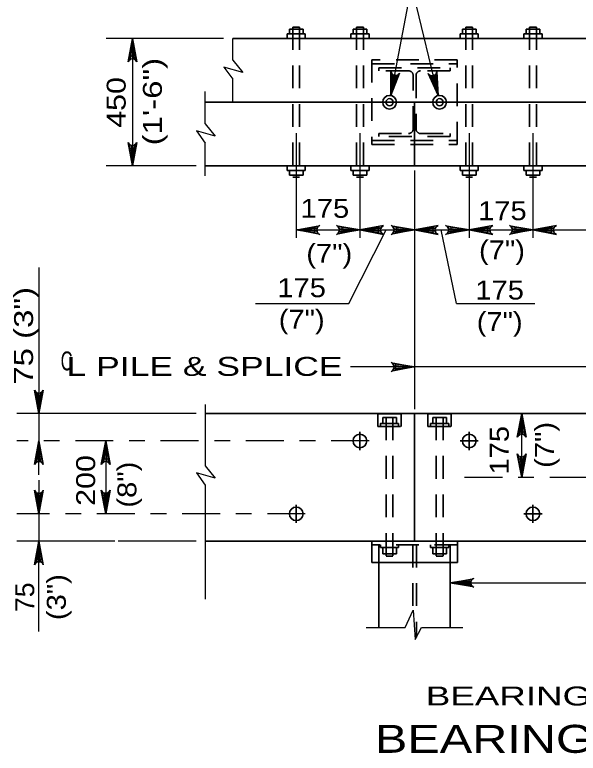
# Model space of a CAD drawing. Extents: x -6.4 to 73.1, y -66 to 0.
# Drawn here: x 57.112 to 60.681, y -50.985 to -46.309 of the extents above; entities that cross this region are included whole.
import ezdxf
from ezdxf.enums import TextEntityAlignment as Align

# ---------------------------------------------------------------- set-up
doc = ezdxf.new("R2010")
doc.units = 0
doc.header["$LTSCALE"] = 0.048
doc.linetypes.add('DOT_DASHED', pattern=[7.7, 5, -1.2, 0.3, -1.2])
doc.linetypes.add('MEDIUM_DASHED', pattern=[4.5, 3, -1.5])
for name, color, linetype, lineweight in [('3', 7, 'Continuous', 35), ('4', 7, 'Continuous', 25), ('5', 7, 'Continuous', 25)]:
    doc.layers.add(name, color=color, linetype=linetype, lineweight=lineweight)

msp = doc.modelspace()

# ---------------------------------------------------------------- hatches: boundary and pattern name
at = {"layer": '4'}
for points in [[(57.83867, -46.56917), (57.87558, -46.56917), (57.85717, -46.4585)], [(57.83867, -47.15508), (57.87558, -47.15508), (57.85717, -47.26583)], [(59.00967, -47.652), (59.00967, -47.69042), (58.89433, -47.67117)], [(59.18267, -47.652), (59.18267, -47.69042), (59.298, -47.67117)], [(59.41333, -47.652), (59.41333, -47.69042), (59.298, -47.67117)], [(59.52867, -47.652), (59.52867, -47.69042), (59.64408, -47.67117)], [(59.75942, -47.652), (59.75942, -47.69042), (59.64408, -47.67117)], [(59.87475, -47.652), (59.87475, -47.69042), (59.99008, -47.67117)], [(60.10542, -47.652), (60.10542, -47.69042), (59.99008, -47.67117)], [(60.27842, -47.652), (60.27842, -47.69042), (60.39375, -47.67117)], [(60.50908, -47.652), (60.50908, -47.69042), (60.39375, -47.67117)], [(59.52392, -48.51992), (59.52392, -48.55842), (59.63925, -48.53917)], [(57.28358, -48.71942), (57.24517, -48.71942), (57.26433, -48.83475)], [(60.30333, -48.95008), (60.34175, -48.95008), (60.3225, -48.83475)], [(57.28358, -49.12308), (57.24517, -49.12308), (57.26433, -49.00775)], [(57.70708, -49.12308), (57.66858, -49.12308), (57.68783, -49.00775)], [(60.34175, -49.12308), (60.30333, -49.12308), (60.3225, -49.2385)], [(57.28358, -49.35383), (57.24517, -49.35383), (57.26433, -49.46917)], [(57.70708, -49.35383), (57.66858, -49.35383), (57.68783, -49.46917)], [(57.28358, -49.7575), (57.24517, -49.7575), (57.26433, -49.64217)]]:
    msp.add_hatch(color=256, dxfattribs=at).paths.add_polyline_path(points)

# ---------------------------------------------------------------- linework, layer by layer
at = {"layer": '3'}
for p, q in [((58.87267, -46.38633), (58.91592, -46.38633)), ((59.27642, -46.38633), (59.31967, -46.38633)), ((59.96842, -46.38633), (60.01167, -46.38633)), ((60.37217, -46.38633), (60.41542, -46.38633)), ((58.83667, -46.42958), (58.952, -46.42958)), ((58.83667, -46.4585), (58.83667, -46.42958)), ((58.85108, -46.40075), (58.93758, -46.40075)), ((58.85108, -46.42958), (58.85108, -46.40075)), ((58.93758, -46.42958), (58.93758, -46.40075)), ((58.952, -46.4585), (58.952, -46.42958)), ((59.25475, -46.42958), (59.25475, -46.40075)), ((59.25475, -46.40075), (59.34125, -46.40075)), ((59.34125, -46.42958), (59.34125, -46.40075)), ((59.35567, -46.4585), (59.35567, -46.42958)), ((59.93242, -46.42958), (60.04775, -46.42958)), ((59.93242, -46.4585), (59.93242, -46.42958)), ((59.94683, -46.42958), (59.94683, -46.40075)), ((59.94683, -46.40075), (60.03333, -46.40075)), ((60.03333, -46.42958), (60.03333, -46.40075)), ((60.04775, -46.4585), (60.04775, -46.42958)), ((60.33608, -46.4585), (60.33608, -46.42958)), ((60.33608, -46.42958), (60.45142, -46.42958)), ((60.3505, -46.42958), (60.3505, -46.40075)), ((60.3505, -46.40075), (60.437, -46.40075)), ((60.437, -46.42958), (60.437, -46.40075)), ((60.45142, -46.4585), (60.45142, -46.42958)), ((64.62167, -46.4585), (58.49208, -46.4585)), ((64.79608, -46.86217), (58.31758, -46.86217)), ((59.64408, -46.86217), (59.64408, -47.26583)), ((64.79608, -47.26583), (58.31758, -47.26583)), ((58.83667, -47.26583), (58.83667, -47.29467)), ((58.952, -47.26583), (58.952, -47.29467)), ((59.24033, -47.26583), (59.24033, -47.29467)), ((59.35567, -47.26583), (59.35567, -47.29467)), ((59.93242, -47.26583), (59.93242, -47.29467)), ((60.04775, -47.26583), (60.04775, -47.29467)), ((60.33608, -47.26583), (60.33608, -47.29467)), ((60.45142, -47.26583), (60.45142, -47.29467)), ((58.83667, -47.29467), (58.952, -47.29467)), ((58.85108, -47.29467), (58.85108, -47.3235)), ((58.85108, -47.3235), (58.93758, -47.3235)), ((58.93758, -47.29467), (58.93758, -47.3235)), ((59.24033, -47.29467), (59.35567, -47.29467)), ((59.25475, -47.29467), (59.25475, -47.3235)), ((59.25475, -47.3235), (59.34125, -47.3235)), ((59.34125, -47.29467), (59.34125, -47.3235)), ((59.93242, -47.29467), (60.04775, -47.29467)), ((59.94683, -47.29467), (59.94683, -47.3235)), ((59.94683, -47.3235), (60.03333, -47.3235)), ((60.03333, -47.29467), (60.03333, -47.3235)), ((60.33608, -47.29467), (60.45142, -47.29467)), ((60.3505, -47.29467), (60.3505, -47.3235)), ((60.3505, -47.3235), (60.437, -47.3235)), ((60.437, -47.29467), (60.437, -47.3235)), ((58.87267, -47.33792), (58.91592, -47.33792)), ((59.27642, -47.33792), (59.31967, -47.33792)), ((59.96842, -47.33792), (60.01167, -47.33792)), ((60.37217, -47.33792), (60.41542, -47.33792)), ((64.79608, -48.83475), (58.31758, -48.83475)), ((59.44225, -48.89808), (59.44225, -48.8585)), ((59.44225, -48.8585), (59.52875, -48.8585)), ((59.52875, -48.89808), (59.52875, -48.8585)), ((59.64408, -48.83475), (59.64408, -49.64217)), ((59.75942, -48.89808), (59.75942, -48.8585)), ((59.75942, -48.8585), (59.84592, -48.8585)), ((59.84592, -48.89808), (59.84592, -48.8585)), ((59.54317, -48.91625), (59.54317, -48.89808)), ((59.86033, -48.91625), (59.86033, -48.89808)), ((59.298, -48.95008), (59.298, -49.06542)), ((59.99008, -48.95008), (59.99008, -49.06542)), ((60.04775, -49.00775), (59.93242, -49.00775)), ((58.89433, -49.4115), (58.89433, -49.52683)), ((60.39375, -49.4115), (60.39375, -49.52683)), ((60.45142, -49.46917), (60.33608, -49.46917)), ((64.79608, -49.64217), (58.31758, -49.64217)), ((59.37325, -49.64217), (59.37325, -49.77717)), ((59.42783, -49.66467), (59.42783, -49.68275)), ((59.54317, -49.66467), (59.54317, -49.68275)), ((59.745, -49.66467), (59.745, -49.68275)), ((59.86033, -49.66467), (59.86033, -49.68275)), ((59.91492, -49.64217), (59.91492, -49.77717)), ((59.42783, -49.68275), (59.54317, -49.68275)), ((59.44225, -49.68275), (59.44225, -49.72233)), ((59.52875, -49.68275), (59.52875, -49.72233)), ((59.745, -49.68275), (59.86033, -49.68275)), ((59.75942, -49.68275), (59.75942, -49.72233)), ((59.84592, -49.68275), (59.84592, -49.72233)), ((59.44225, -49.72233), (59.52875, -49.72233)), ((59.46392, -49.73675), (59.50717, -49.73675)), ((59.75942, -49.72233), (59.84592, -49.72233)), ((59.78108, -49.73675), (59.82433, -49.73675)), ((59.91492, -49.77717), (59.37325, -49.77717)), ((59.41825, -49.77717), (59.41825, -50.18858)), ((59.86992, -49.77717), (59.86992, -50.18858))]:
    msp.add_line(p, q, dxfattribs=at)
at = {"layer": '3', "linetype": 'MEDIUM_DASHED'}
for p, q in [((58.87267, -46.38633), (58.87267, -47.33792)), ((58.91592, -46.38633), (58.91592, -47.33792)), ((59.27642, -46.38633), (59.27642, -47.33792)), ((59.31967, -46.38633), (59.31967, -47.33792)), ((59.96842, -46.38633), (59.96842, -47.33792)), ((60.01167, -46.38633), (60.01167, -47.33792)), ((60.37217, -46.38633), (60.37217, -47.33792)), ((60.41542, -46.38633), (60.41542, -47.33792)), ((59.37342, -46.61933), (59.91475, -46.61933)), ((59.63475, -47.032), (59.63475, -46.69233)), ((59.65342, -46.69233), (59.65342, -47.032)), ((59.37342, -47.105), (59.91475, -47.105)), ((59.46392, -48.8585), (59.46392, -49.73675)), ((59.50717, -48.8585), (59.50717, -49.73675)), ((59.78108, -48.8585), (59.78108, -49.73675)), ((59.82433, -48.8585), (59.82433, -49.73675)), ((59.91492, -49.66467), (59.37325, -49.66467)), ((59.41825, -49.66467), (59.41825, -49.77717)), ((59.63283, -49.66467), (59.63283, -50.08625)), ((59.65533, -49.66467), (59.65533, -50.25058)), ((59.86992, -49.66467), (59.86992, -49.77717))]:
    msp.add_line(p, q, dxfattribs=at)
at = {"layer": '3', "lineweight": 25}
for p, q in [((58.49208, -46.59625), (58.49208, -46.4585)), ((58.49208, -46.59625), (58.55542, -46.67417)), ((58.43617, -46.64042), (58.49208, -46.717)), ((58.55542, -46.67417), (58.43617, -46.64042)), ((58.49208, -46.86217), (58.49208, -46.717)), ((58.31758, -46.99992), (58.31758, -46.79483)), ((58.31758, -46.99992), (58.381, -47.07792)), ((58.31758, -47.32908), (58.31758, -47.12067)), ((58.31758, -48.77708), (58.31758, -49.166)), ((58.31758, -49.166), (58.381, -49.244)), ((58.26175, -49.21017), (58.31758, -49.28675)), ((58.381, -49.244), (58.26175, -49.21017)), ((58.31758, -49.28675), (58.31758, -50.00908)), ((59.33783, -50.18858), (59.58458, -50.18858))]:
    msp.add_line(p, q, dxfattribs=at)
at = {"layer": '3'}
for points in [[(59.24033, -46.4585), (59.24033, -46.42958), (59.35567, -46.42958)], [(59.42783, -48.91625), (59.42783, -48.89808), (59.54317, -48.89808)], [(59.745, -48.91625), (59.745, -48.89808), (59.86033, -48.89808)]]:
    msp.add_lwpolyline(points, dxfattribs=at)
at = {"layer": '3', "linetype": 'MEDIUM_DASHED'}
for points in [[(59.37342, -47.13117), (59.91475, -47.13117), (59.91475, -46.59317), (59.37342, -46.59317)], [(59.41167, -48.91625), (59.55933, -48.91625), (59.55933, -48.83483), (59.41167, -48.83483)], [(59.72883, -48.91625), (59.8765, -48.91625), (59.8765, -48.83483), (59.72883, -48.83483)]]:
    msp.add_lwpolyline(points, close=True, dxfattribs=at)
for points in [[(59.41825, -46.64475), (59.86992, -46.64475), (59.86992, -46.66358), (59.68217, -46.66358)], [(59.606, -46.66358), (59.41825, -46.66358), (59.41825, -46.64475)], [(59.68217, -47.06075), (59.86992, -47.06075), (59.86992, -47.07958), (59.41825, -47.07958), (59.41825, -47.06075), (59.606, -47.06075)]]:
    msp.add_lwpolyline(points, dxfattribs=at)
at = {"layer": '3', "lineweight": 25}
for points in [[(58.381, -47.07792), (58.26175, -47.04408), (58.31758, -47.12067)], [(59.58458, -50.18858), (59.63617, -50.07917), (59.6475, -50.26542), (59.68817, -50.18858), (59.94942, -50.18858)]]:
    msp.add_lwpolyline(points, dxfattribs=at)
at = {"layer": '3'}
for centre, radius in [((59.4855, -46.86217), 0.04325), ((59.4855, -46.86217), 0.02242), ((59.80267, -46.86217), 0.04325), ((59.80267, -46.86217), 0.02242), ((59.29804, -49.00774), 0.04325), ((59.99009, -49.00774), 0.04325), ((58.89435, -49.46911), 0.04325), ((60.39379, -49.46911), 0.04325)]:
    msp.add_circle(centre, radius, dxfattribs=at)
at = {"layer": '3', "linetype": 'MEDIUM_DASHED'}
for centre, start, end in [((59.60597, -46.69236), 0, 90), ((59.68219, -46.69236), 90, 180), ((59.60597, -47.03197), 270, 0), ((59.68219, -47.03197), 180, 270)]:
    msp.add_arc(centre, 0.02881, start, end, dxfattribs=at)
at = {"layer": '4'}
for p, q in [((59.49358, -46.81967), (59.62642, -46.12508)), ((59.79258, -46.82008), (59.62642, -46.12508)), ((58.43442, -46.4585), (57.69108, -46.4585)), ((57.85717, -46.4585), (57.85717, -47.26583)), ((58.89433, -47.05917), (58.89433, -47.72075)), ((59.298, -47.05917), (59.298, -47.72075)), ((59.99008, -47.05917), (59.99008, -47.72075)), ((60.39375, -47.05917), (60.39375, -47.72075)), ((58.25992, -47.26583), (57.69108, -47.26583)), ((59.64408, -47.29467), (59.64408, -48.80592)), ((58.89433, -47.67117), (61.55683, -47.67117)), ((59.90917, -48.13783), (59.81175, -47.67108)), ((57.26433, -47.90908), (57.26433, -48.83475)), ((59.90917, -48.13783), (60.40617, -48.13783)), ((63.46975, -48.53908), (59.23808, -48.53908)), ((58.25992, -48.83475), (57.12367, -48.83475)), ((57.26433, -48.83475), (57.26433, -49.00775)), ((60.3225, -49.2385), (60.3225, -48.83475)), ((57.26433, -49.22225), (57.26433, -49.00775)), ((57.68783, -49.00775), (57.68783, -49.46917)), ((57.26433, -49.25542), (57.26433, -49.46917)), ((57.26433, -49.46917), (57.26433, -49.64217)), ((57.74542, -49.64217), (57.12367, -49.64217)), ((57.26433, -50.21358), (57.26433, -49.64217)), ((58.25992, -49.64217), (57.76583, -49.64217)), ((59.86992, -49.90558), (60.852, -49.9055))]:
    msp.add_line(p, q, dxfattribs=at)
at = {"layer": '4', "linetype": 'DOT_DASHED'}
for p, q in [((59.35567, -49.00775), (57.12367, -49.00775)), ((62.90008, -49.2385), (59.867, -49.2385)), ((58.952, -49.46917), (57.12367, -49.46917))]:
    msp.add_line(p, q, dxfattribs=at)
at = {"layer": '4'}
for points in [[(57.85717, -46.4585), (57.88517, -46.60767), (57.87717, -46.59617), (57.86717, -46.59025), (57.85717, -46.5885), (57.84717, -46.59025), (57.83717, -46.59617), (57.82917, -46.60767), (57.85717, -46.4585), (57.83717, -46.59617), (57.84717, -46.59025), (57.85717, -46.4585), (57.85717, -46.5885), (57.86717, -46.59025), (57.85717, -46.4585), (57.87717, -46.59617)], [(59.49358, -46.81967), (59.49417, -46.66792), (59.497, -46.67433), (59.49983, -46.68067), (59.50417, -46.68458), (59.5085, -46.68842), (59.51325, -46.69017), (59.518, -46.692), (59.52308, -46.69208), (59.52817, -46.69217), (59.53358, -46.69017), (59.53908, -46.68825), (59.54408, -46.68333), (59.54908, -46.67842), (59.49358, -46.81967), (59.54408, -46.68333), (59.53908, -46.68825), (59.49358, -46.81967), (59.53358, -46.69017), (59.52817, -46.69217), (59.49358, -46.81967), (59.52308, -46.69208), (59.518, -46.692), (59.49358, -46.81967), (59.51325, -46.69017), (59.5085, -46.68842), (59.49358, -46.81967), (59.50417, -46.68458), (59.49983, -46.68067), (59.49358, -46.81967), (59.497, -46.67433)], [(59.79258, -46.82008), (59.73067, -46.6815), (59.73592, -46.68617), (59.74108, -46.69083), (59.74667, -46.69258), (59.75225, -46.69425), (59.75725, -46.69392), (59.76233, -46.69367), (59.767, -46.69167), (59.77167, -46.68967), (59.77583, -46.68558), (59.78, -46.68158), (59.78258, -46.675), (59.78508, -46.6685), (59.79258, -46.82008), (59.78258, -46.675), (59.78, -46.68158), (59.79258, -46.82008), (59.77583, -46.68558), (59.77167, -46.68967), (59.79258, -46.82008), (59.767, -46.69167), (59.76233, -46.69367), (59.79258, -46.82008), (59.75725, -46.69392), (59.75225, -46.69425), (59.79258, -46.82008), (59.74667, -46.69258), (59.74108, -46.69083), (59.79258, -46.82008), (59.73592, -46.68617)], [(57.85717, -47.26583), (57.82917, -47.11667), (57.83717, -47.12817), (57.84717, -47.13408), (57.85717, -47.13583), (57.86717, -47.13408), (57.87717, -47.12817), (57.88517, -47.11667), (57.85717, -47.26583), (57.87717, -47.12817), (57.86717, -47.13408), (57.85717, -47.26583), (57.85717, -47.13583), (57.84717, -47.13408), (57.85717, -47.26583), (57.83717, -47.12817)], [(58.89433, -47.67117), (59.0435, -47.64317), (59.032, -47.65117), (59.02608, -47.66117), (59.02433, -47.67117), (59.02608, -47.68117), (59.032, -47.69117), (59.0435, -47.69917), (58.89433, -47.67117), (59.032, -47.69117), (59.02608, -47.68117), (58.89433, -47.67117), (59.02433, -47.67117), (59.02608, -47.66117), (58.89433, -47.67117), (59.032, -47.65117)], [(59.298, -47.67117), (59.14883, -47.69917), (59.16033, -47.69117), (59.16625, -47.68117), (59.168, -47.67117), (59.16625, -47.66117), (59.16033, -47.65117), (59.14883, -47.64317), (59.298, -47.67117), (59.16033, -47.65117), (59.16625, -47.66117), (59.298, -47.67117), (59.168, -47.67117), (59.16625, -47.68117), (59.298, -47.67117), (59.16033, -47.69117)], [(59.298, -47.67117), (59.44717, -47.69917), (59.43567, -47.69117), (59.42975, -47.68117), (59.428, -47.67117), (59.42975, -47.66117), (59.43567, -47.65117), (59.44717, -47.64317), (59.298, -47.67117), (59.43567, -47.65117), (59.42975, -47.66117), (59.298, -47.67117), (59.428, -47.67117), (59.42975, -47.68117), (59.298, -47.67117), (59.43567, -47.69117)], [(59.64408, -47.67117), (59.49492, -47.69917), (59.50642, -47.69117), (59.51233, -47.68117), (59.51408, -47.67117), (59.51233, -47.66117), (59.50642, -47.65117), (59.49492, -47.64317), (59.64408, -47.67117), (59.50642, -47.65117), (59.51233, -47.66117), (59.64408, -47.67117), (59.51408, -47.67117), (59.51233, -47.68117), (59.64408, -47.67117), (59.50642, -47.69117)], [(59.64408, -47.67117), (59.79325, -47.69917), (59.78175, -47.69117), (59.77583, -47.68117), (59.77408, -47.67117), (59.77583, -47.66117), (59.78175, -47.65117), (59.79325, -47.64317), (59.64408, -47.67117), (59.78175, -47.65117), (59.77583, -47.66117), (59.64408, -47.67117), (59.77408, -47.67117), (59.77583, -47.68117), (59.64408, -47.67117), (59.78175, -47.69117)], [(59.99008, -47.67117), (59.84092, -47.69917), (59.85242, -47.69117), (59.85833, -47.68117), (59.86008, -47.67117), (59.85833, -47.66117), (59.85242, -47.65117), (59.84092, -47.64317), (59.99008, -47.67117), (59.85242, -47.65117), (59.85833, -47.66117), (59.99008, -47.67117), (59.86008, -47.67117), (59.85833, -47.68117), (59.99008, -47.67117), (59.85242, -47.69117)], [(59.99008, -47.67117), (60.13925, -47.69917), (60.12775, -47.69117), (60.12183, -47.68117), (60.12008, -47.67117), (60.12183, -47.66117), (60.12775, -47.65117), (60.13925, -47.64317), (59.99008, -47.67117), (60.12775, -47.65117), (60.12183, -47.66117), (59.99008, -47.67117), (60.12008, -47.67117), (60.12183, -47.68117), (59.99008, -47.67117), (60.12775, -47.69117)], [(60.39375, -47.67117), (60.24458, -47.69917), (60.25608, -47.69117), (60.262, -47.68117), (60.26375, -47.67117), (60.262, -47.66117), (60.25608, -47.65117), (60.24458, -47.64317), (60.39375, -47.67117), (60.25608, -47.65117), (60.262, -47.66117), (60.39375, -47.67117), (60.26375, -47.67117), (60.262, -47.68117), (60.39375, -47.67117), (60.25608, -47.69117)], [(60.39375, -47.67117), (60.54292, -47.69917), (60.53142, -47.69117), (60.5255, -47.68117), (60.52375, -47.67117), (60.5255, -47.66117), (60.53142, -47.65117), (60.54292, -47.64317), (60.39375, -47.67117), (60.53142, -47.65117), (60.5255, -47.66117), (60.39375, -47.67117), (60.52375, -47.67117), (60.5255, -47.68117), (60.39375, -47.67117), (60.53142, -47.69117)], [(58.63633, -48.13783), (59.22733, -48.13783), (59.46508, -47.67108)], [(59.64408, -48.53917), (59.49492, -48.56717), (59.50642, -48.55917), (59.51233, -48.54917), (59.51408, -48.53917), (59.51233, -48.52917), (59.50642, -48.51917), (59.49492, -48.51117), (59.64408, -48.53917), (59.50642, -48.51917), (59.51233, -48.52917), (59.64408, -48.53917), (59.51408, -48.53917), (59.51233, -48.54917), (59.64408, -48.53917), (59.50642, -48.55917)], [(57.26433, -48.83475), (57.23633, -48.68558), (57.24433, -48.69708), (57.25433, -48.703), (57.26433, -48.70475), (57.27433, -48.703), (57.28433, -48.69708), (57.29233, -48.68558), (57.26433, -48.83475), (57.28433, -48.69708), (57.27433, -48.703), (57.26433, -48.83475), (57.26433, -48.70475), (57.25433, -48.703), (57.26433, -48.83475), (57.24433, -48.69708)], [(60.3225, -48.83475), (60.3505, -48.98392), (60.3425, -48.97242), (60.3325, -48.9665), (60.3225, -48.96475), (60.3125, -48.9665), (60.3025, -48.97242), (60.2945, -48.98392), (60.3225, -48.83475), (60.3025, -48.97242), (60.3125, -48.9665), (60.3225, -48.83475), (60.3225, -48.96475), (60.3325, -48.9665), (60.3225, -48.83475), (60.3425, -48.97242)], [(57.26433, -49.00775), (57.29233, -49.15692), (57.28433, -49.14542), (57.27433, -49.1395), (57.26433, -49.13775), (57.25433, -49.1395), (57.24433, -49.14542), (57.23633, -49.15692), (57.26433, -49.00775), (57.24433, -49.14542), (57.25433, -49.1395), (57.26433, -49.00775), (57.26433, -49.13775), (57.27433, -49.1395), (57.26433, -49.00775), (57.28433, -49.14542)], [(57.68783, -49.00775), (57.71583, -49.15692), (57.70783, -49.14542), (57.69783, -49.1395), (57.68783, -49.13775), (57.67783, -49.1395), (57.66783, -49.14542), (57.65983, -49.15692), (57.68783, -49.00775), (57.66783, -49.14542), (57.67783, -49.1395), (57.68783, -49.00775), (57.68783, -49.13775), (57.69783, -49.1395), (57.68783, -49.00775), (57.70783, -49.14542)], [(60.3225, -49.2385), (60.2945, -49.08933), (60.3025, -49.10083), (60.3125, -49.10675), (60.3225, -49.1085), (60.3325, -49.10675), (60.3425, -49.10083), (60.3505, -49.08933), (60.3225, -49.2385), (60.3425, -49.10083), (60.3325, -49.10675), (60.3225, -49.2385), (60.3225, -49.1085), (60.3125, -49.10675), (60.3225, -49.2385), (60.3025, -49.10083)], [(57.26433, -49.46917), (57.23633, -49.32), (57.24433, -49.3315), (57.25433, -49.33742), (57.26433, -49.33917), (57.27433, -49.33742), (57.28433, -49.3315), (57.29233, -49.32), (57.26433, -49.46917), (57.28433, -49.3315), (57.27433, -49.33742), (57.26433, -49.46917), (57.26433, -49.33917), (57.25433, -49.33742), (57.26433, -49.46917), (57.24433, -49.3315)], [(57.68783, -49.46917), (57.65983, -49.32), (57.66783, -49.3315), (57.67783, -49.33742), (57.68783, -49.33917), (57.69783, -49.33742), (57.70783, -49.3315), (57.71583, -49.32), (57.68783, -49.46917), (57.70783, -49.3315), (57.69783, -49.33742), (57.68783, -49.46917), (57.68783, -49.33917), (57.67783, -49.33742), (57.68783, -49.46917), (57.66783, -49.3315)], [(57.26433, -49.64217), (57.29233, -49.79133), (57.28433, -49.77983), (57.27433, -49.77392), (57.26433, -49.77217), (57.25433, -49.77392), (57.24433, -49.77983), (57.23633, -49.79133), (57.26433, -49.64217), (57.24433, -49.77983), (57.25433, -49.77392), (57.26433, -49.64217), (57.26433, -49.77217), (57.27433, -49.77392), (57.26433, -49.64217), (57.28433, -49.77983)], [(59.86992, -49.90558), (60.01908, -49.87758), (60.01333, -49.88158), (60.00758, -49.88558), (60.00458, -49.89058), (60.00167, -49.89558), (60.00083, -49.90058), (59.99992, -49.90558), (60.00083, -49.91058), (60.00167, -49.91558), (60.00458, -49.92058), (60.00758, -49.92558), (60.01333, -49.92958), (60.01908, -49.9335), (59.86992, -49.90558), (60.01333, -49.92958), (60.00758, -49.92558), (59.86992, -49.90558), (60.00458, -49.92058), (60.00167, -49.91558), (59.86992, -49.90558), (60.00083, -49.91058), (59.99992, -49.90558), (59.86992, -49.90558), (60.00083, -49.90058), (60.00167, -49.89558), (59.86992, -49.90558), (60.00458, -49.89058), (60.00758, -49.88558), (59.86992, -49.90558), (60.01333, -49.88158)]]:
    msp.add_lwpolyline(points, dxfattribs=at)
for points in [[(57.83867, -46.56917), (57.87558, -46.56917), (57.85717, -46.4585)], [(57.83867, -47.15508), (57.87558, -47.15508), (57.85717, -47.26583)], [(59.00967, -47.652), (59.00967, -47.69042), (58.89433, -47.67117)], [(59.18267, -47.652), (59.18267, -47.69042), (59.298, -47.67117)], [(59.41333, -47.652), (59.41333, -47.69042), (59.298, -47.67117)], [(59.52867, -47.652), (59.52867, -47.69042), (59.64408, -47.67117)], [(59.75942, -47.652), (59.75942, -47.69042), (59.64408, -47.67117)], [(59.87475, -47.652), (59.87475, -47.69042), (59.99008, -47.67117)], [(60.10542, -47.652), (60.10542, -47.69042), (59.99008, -47.67117)], [(60.27842, -47.652), (60.27842, -47.69042), (60.39375, -47.67117)], [(60.50908, -47.652), (60.50908, -47.69042), (60.39375, -47.67117)], [(59.52392, -48.51992), (59.52392, -48.55842), (59.63925, -48.53917)], [(57.28358, -48.71942), (57.24517, -48.71942), (57.26433, -48.83475)], [(60.30333, -48.95008), (60.34175, -48.95008), (60.3225, -48.83475)], [(57.28358, -49.12308), (57.24517, -49.12308), (57.26433, -49.00775)], [(57.70708, -49.12308), (57.66858, -49.12308), (57.68783, -49.00775)], [(60.34175, -49.12308), (60.30333, -49.12308), (60.3225, -49.2385)], [(57.28358, -49.35383), (57.24517, -49.35383), (57.26433, -49.46917)], [(57.70708, -49.35383), (57.66858, -49.35383), (57.68783, -49.46917)], [(57.28358, -49.7575), (57.24517, -49.7575), (57.26433, -49.64217)]]:
    msp.add_lwpolyline(points, close=True, dxfattribs=at)

# ---------------------------------------------------------------- texts
for s, width, p in [('C', 0.65, (57.40225, -48.56067)), ('L PILE & SPLICE', 1.4, (57.43958, -48.59542))]:
    msp.add_text(s, height=0.12, dxfattribs=dict(at, width=width)).set_placement(p)
at = {"layer": '4', "width": 1.3}
msp.add_text('BEARING SILL SPLICE DETAILS', height=0.1772, dxfattribs=at).set_placement((61.72096, -50.98267), align=Align.CENTER)
at = {"layer": '5'}
for s, width, p in [('(1\'-6")', 1.3, (58.04333, -46.8585)), ('450', 1.2, (57.814, -46.86396)), ('(7")', 1.15, (60.52658, -49.03258)), ('175', 1.15, (60.24075, -49.06642)), ('(3")', 1.15, (57.43483, -49.9965)), ('75', 1.05, (57.23483, -49.99742))]:
    msp.add_text(s, height=0.12, rotation=90, dxfattribs=dict(at, width=width)).set_placement(p, align=Align.CENTER)
for s, width, p in [('175', 1.15, (59.07592, -47.59442)), ('175', 1.15, (60.20017, -47.6095)), ('(7")', 1.15, (60.19767, -47.85808)), ('(7")', 1.15, (59.10367, -47.87933)), ('175', 1.15, (58.92858, -48.097)), ('175', 1.15, (60.18267, -48.11192)), ('(7")', 1.15, (58.92908, -48.297)), ('(7")', 1.15, (60.18317, -48.31192)), ('BEARING SILL: 2-225x350 (9"x14")', 1.45, (61.56967, -50.68283))]:
    msp.add_text(s, height=0.12, dxfattribs=dict(at, width=width)).set_placement(p, align=Align.CENTER)
for s, width, p in [('75 (3")', 1.3, (57.22733, -48.65133)), ('200', 1.2, (57.6205, -49.41858)), ('(8")', 1.15, (57.88183, -49.42992))]:
    msp.add_text(s, height=0.12, rotation=90, dxfattribs=dict(at, width=width)).set_placement(p)

doc.saveas('drawing.dxf')
